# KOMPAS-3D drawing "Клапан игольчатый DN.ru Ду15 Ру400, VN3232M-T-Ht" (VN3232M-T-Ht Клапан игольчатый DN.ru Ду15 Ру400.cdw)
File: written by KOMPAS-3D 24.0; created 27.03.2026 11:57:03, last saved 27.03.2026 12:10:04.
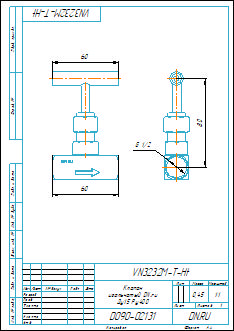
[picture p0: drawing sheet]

Document properties: Автор: Илья; Форматы листов документа: A4; Полное имя файла: VN3232M-T-Ht Клапан игольчатый DN.ru Ду15 Ру400.m3d; Масса: 0.45; Наименование: Клапан игольчатый DN.ru Ду15 Ру400; Количество листов документа: 1; Примечание: D090-02131

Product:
- Body: Body3  | qty 1
    Масса: 0.224966
- Body: Body6  | qty 1
    Масса: 0.282571
- Part/product: Клапан игольчатый DN.ru Ду15 Ру400  | designation VN3232M-T-Ht
    Масса: 0.45
    Раздел спецификации: Прочие изделия
    Примечание: D090-02131

Views: Вид 1, Слева, Проекционный вид 2
Referenced files in D:\Обмен\Заказы с фриланса\DN.ru\VNxxM-T-Ht Клапан игольчатый DN.ru Ду8-50 Ру400\VN3232M-T-Ht Клапан игольчатый DN.ru Ду8-50 Ру400\DN8\: VN3232M-T-Ht Клапан игольчатый DN.ru Ду8 Ру400.m3d, VN3232M-T-Ht Клапан игольчатый DN.ru Ду8 Ру400.cdw
Referenced files in D:\Обмен\Заказы с фриланса\DN.ru\VNxxM-T-Ht Клапан игольчатый DN.ru Ду8-50 Ру400\VN3232M-T-Ht Клапан игольчатый DN.ru Ду8-50 Ру400\DN15\: VN3232M-T-Ht Клапан игольчатый DN.ru Ду15 Ру400.m3d
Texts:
  VN3232M-T-Ht
  Клапан
  игольчатый DN.ru
  Ду15 Ру400
  Body6
  Клапан игольчатый DN.ru Ду15 Ру400
  VN3232M-T-Ht Клапан игольчатый DN.ru Ду15 Ру400
Dimensions and other numbers on the sheet: 0; 3; 2; 4; 60; 80; 1:1; 1; 0,45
